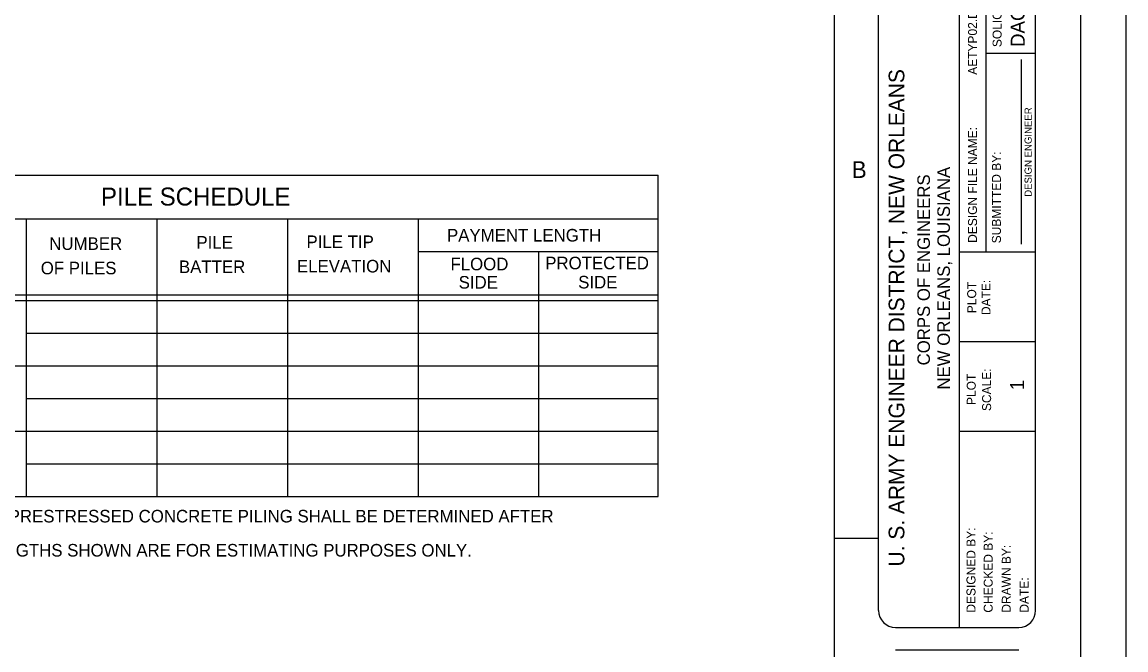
# Model space of a CAD drawing. Extents: x 44742.26 to 44749.63, y 44739 to 44741.19.
# Drawn here: x 44744.296 to 44745.087, y 44739.485 to 44739.935 of the extents above; entities that cross this region are included whole.
import ezdxf

# ---------------------------------------------------------------- set-up
doc = ezdxf.new("R2010")
doc.units = 0
for name, color, linetype in [('Level 1', 7, 'Continuous'), ('Level 10', 7, 'Continuous'), ('Level 2', 7, 'Continuous'), ('Level 4', 7, 'Continuous'), ('Level 7', 7, 'Continuous'), ('Level 9', 7, 'Continuous')]:
    doc.layers.add(name, color=color, linetype=linetype)

msp = doc.modelspace()

# ---------------------------------------------------------------- linework, layer by layer
at = {"layer": 'Level 1'}
for p, q in [((44744.96775, 44740.03941), (44744.96775, 44739.50118)), ((44744.29894, 44739.59514), (44744.29894, 44739.79428)), ((44744.39265, 44739.59514), (44744.39265, 44739.79428)), ((44744.48637, 44739.59514), (44744.48637, 44739.79428)), ((44744.58008, 44739.59514), (44744.58008, 44739.79428)), ((44744.58008, 44739.77085), (44744.75189, 44739.77085)), ((44744.66598, 44739.77085), (44744.66598, 44739.59514)), ((44744.29894, 44739.71228), (44744.75189, 44739.71228)), ((44744.29894, 44739.66542), (44744.75189, 44739.66542)), ((44744.29894, 44739.61857), (44744.75189, 44739.61857))]:
    msp.add_line(p, q, dxfattribs=at)
msp.add_lwpolyline([(44742.25988, 44741.18835), (44745.08727, 44741.18835), (44745.08727, 44739.00305), (44742.25988, 44739.00305)], close=True, dxfattribs=at)
for points in [[(44744.90992, 44739.51323), (44744.90992, 44740.02736)], [(44745.0225, 44739.51323), (44745.0225, 44740.02736)], [(44744.92197, 44739.50118), (44745.01045, 44739.50118)], [(44744.92197, 44739.48499), (44745.01045, 44739.48499)]]:
    msp.add_lwpolyline(points, dxfattribs=at)
for centre, start, end in [((44744.92197, 44739.51323), 180, 270), ((44745.01045, 44739.51323), 270, 0)]:
    msp.add_arc(centre, 0.01205, start, end, dxfattribs=at)
at = {"layer": 'Level 10'}
msp.add_line((44744.8783, 44739.56518), (44744.90992, 44739.56518), dxfattribs=at)
at = {"layer": 'Level 2'}
for p, q in [((44744.9867, 44740.03941), (44744.9867, 44739.7703)), ((44745.0225, 44739.91272), (44744.9867, 44739.91272)), ((44745.01247, 44739.77613), (44745.01247, 44739.90858)), ((44744.13494, 44739.79428), (44744.75189, 44739.79428)), ((44745.0225, 44739.7703), (44744.96775, 44739.7703)), ((44744.13494, 44739.73961), (44744.75189, 44739.73961)), ((44744.13494, 44739.73571), (44744.75189, 44739.73571)), ((44745.0225, 44739.70604), (44744.96775, 44739.70604)), ((44744.13494, 44739.68885), (44744.75189, 44739.68885)), ((44744.13494, 44739.64199), (44744.75189, 44739.64199)), ((44745.0225, 44739.64178), (44744.96775, 44739.64178))]:
    msp.add_line(p, q, dxfattribs=at)
at = {"layer": 'Level 7'}
for p, q in [((44744.13494, 44739.82552), (44744.75189, 44739.82552)), ((44744.75189, 44739.59514), (44744.75189, 44739.82552)), ((44744.13494, 44739.59514), (44744.75189, 44739.59514))]:
    msp.add_line(p, q, dxfattribs=at)
at = {"layer": 'Level 9'}
msp.add_line((44745.05488, 44739.03544), (44745.05488, 44741.15596), dxfattribs=at)
msp.add_lwpolyline([(44744.8783, 44739.03544), (44744.8783, 44741.15596)], dxfattribs=at)

# ---------------------------------------------------------------- texts
at = {"layer": 'Level 1'}
for s, height, p in [('SOLICITATION NO.', 0.0064263, (44744.9981, 44739.9174)), ('AETYP02.DGN', 0.0064258, (44744.9805, 44739.89754)), ('U. S. ARMY ENGINEER DISTRICT, NEW ORLEANS', 0.0112451, (44744.92838, 44739.54485)), ('DESIGN ENGINEER', 0.0051401, (44745.01971, 44739.81004)), ('DESIGN FILE NAME:', 0.0064263, (44744.98048, 44739.777)), ('SUBMITTED BY:', 0.0064263, (44744.99761, 44739.77667)), ('PLOT', 0.006426, (44744.97988, 44739.72655)), ('DATE:', 0.006426, (44744.99014, 44739.7252)), ('SCALE:', 0.006426, (44744.99058, 44739.65632)), ('PLOT', 0.006426, (44744.97957, 44739.66068)), ('DESIGNED BY:', 0.0064263, (44744.97938, 44739.51171)), ('CHECKED BY:', 0.0064263, (44744.99172, 44739.51171)), ('DRAWN BY:', 0.006426, (44745.00469, 44739.51171)), ('DATE:', 0.006426, (44745.01753, 44739.51171))]:
    msp.add_text(s, height=height, rotation=90, dxfattribs=at).set_placement(p)
msp.add_text('B', height=0.01203, dxfattribs=at).set_placement((44744.89064, 44739.8235))
at = {"layer": 'Level 10'}
msp.add_text('PILE SCHEDULE', height=0.0128758, dxfattribs=at).set_placement((44744.35224, 44739.80376))
at = {"layer": 'Level 4'}
for s, p in [('NOTE: EXACT LENGTHS OF PRESTRESSED CONCRETE PILING SHALL BE DETERMINED AFTER', (44744.12187, 44739.57643)), ('       PILE TESTS ARE CONDUCTED. LENGTHS SHOWN ARE FOR ESTIMATING PURPOSES ONLY.', (44744.0606, 44739.55198))]:
    msp.add_text(s, height=0.0090203, dxfattribs=at).set_placement(p)
at = {"layer": 'Level 7'}
for s, height, p in [('DACW29-', 0.010024, (44745.01468, 44739.91748)), ('NEW ORLEANS, LOUISIANA', 0.0089961, (44744.96104, 44739.67175)), ('CORPS OF ENGINEERS', 0.0089961, (44744.94671, 44739.68908)), ('1', 0.01002, (44745.01425, 44739.67127))]:
    msp.add_text(s, height=height, rotation=90, dxfattribs=at).set_placement(p)
for s, height, p in [('NUMBER', 0.00902, (44744.31519, 44739.77191)), ('PILE', 0.00902, (44744.42071, 44739.77281)), ('PILE TIP', 0.00902, (44744.49965, 44739.77325)), ('PAYMENT LENGTH', 0.0090203, (44744.60041, 44739.77794)), ('BATTER', 0.00902, (44744.40817, 44739.75532)), ('ELEVATION', 0.00902, (44744.4928, 44739.75576)), ('FLOOD', 0.00902, (44744.60288, 44739.7573)), ('PROTECTED', 0.00902, (44744.67084, 44739.75801)), ('OF PILES', 0.00902, (44744.30908, 44739.75442)), ('SIDE', 0.00902, (44744.60876, 44739.74418)), ('SIDE', 0.00902, (44744.69447, 44739.74428))]:
    msp.add_text(s, height=height, dxfattribs=at).set_placement(p)

doc.saveas('drawing.dxf')
